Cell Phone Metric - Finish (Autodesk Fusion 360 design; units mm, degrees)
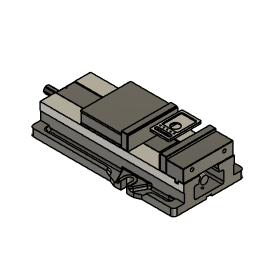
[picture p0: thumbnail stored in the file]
description: HaasClamp
derived_base_feature "Derived Base Feature" bodies "Main Body"
align "Align1"
sketch "Sketch1" plane through (0, 0, 0) normal (0, 0, -1) x axis (1, 0, 0)
  line L1 (30, 46.5) -> (30, -46.5)
  line L2 (-26.5, 50) -> (26.5, 50)
  line L3 (-30, -46.5) -> (-30, 46.5)
  line L4 (26.5, -50) -> (-26.5, -50)
  line L5 (-23.5, 38.5) -> (-23.5, 36)
  line L6 (20, 42) -> (-20, 42)
  line L7 (23.5, 36) -> (23.5, 38.5)
  line L8 (-20, 32.5) -> (20, 32.5)
  line L9 (-50.8, -55) -> (50.8, -55)
  line L10 (-50.8, 55) -> (-50.8, -55)
  line L11 (50.8, 55) -> (-50.8, 55)
  line L12 (50.8, -55) -> (50.8, 55)
  line L13 (-50.8, 55) -> (50.8, -55)
  line L14 (50.8, 55) -> (-50.8, -55)
  arc A1 centre (26.5, -46.5) radius 3.5 clockwise from (30, -46.5) to (26.5, -50)
  arc A2 centre (26.5, 46.5) radius 3.5 clockwise from (26.5, 50) to (30, 46.5)
  arc A3 centre (-26.5, 46.5) radius 3.5 clockwise from (-30, 46.5) to (-26.5, 50)
  arc A4 centre (-26.5, -46.5) radius 3.5 clockwise from (-26.5, -50) to (-30, -46.5)
  circle C1 centre (10.5, 25) radius 2.117
  circle C2 centre (-10.5, 25) radius 2.117
  circle C3 centre (-21, 25) radius 2.117
  circle C4 centre (0, 25) radius 2.117
  circle C5 centre (21, 25) radius 2.117
  arc A5 centre (-20, 38.5) radius 3.5 clockwise from (-23.5, 38.5) to (-20, 42)
  arc A6 centre (20, 38.5) radius 3.5 clockwise from (20, 42) to (23.5, 38.5)
  arc A7 centre (20, 36) radius 3.5 clockwise from (23.5, 36) to (20, 32.5)
  arc A8 centre (-20, 36) radius 3.5 clockwise from (-20, 32.5) to (-23.5, 36)
  circle C6 centre (0, 0) radius 12.5
  point P36 (0, 0)
  point P1 (0, 0)
  point P34 (-50.8, 55)
  point P35 (50.8, 55)
  point P32 (50.8, -55)
  horizontal L9
  perpendicular L9 L10
  parallel L9 L11
  parallel L10 L12
  coincident L13 P36
  coincident L14 P36
  coincident P1 P36
  dimension "d1" distance P34 P35 = 101.6
  dimension "d2" distance P32 P35 = 110
extrude "Extrude1" new body sketch "Sketch1" profile of L9 L10 L11 L12 against normal blind 6 bodies "Stock"
base_feature "Base Feature1"
base_feature "Base Feature1"
base_feature "Base Feature1"
base_feature "Base Feature1"
base_feature "Base Feature1"
base_feature "Base Feature1"
base_feature "Base Feature1"
base_feature "Base Feature1"
base_feature "Base Feature1"
base_feature "Base Feature1"
as_built_joint "As-built1"
as_built_joint "As-built2"
as_built_joint "As-built3"
joint_origin "JointOrigin1" OffsetX 0 OffsetY 0 OffsetZ 0 AngleZ 0
joint "Assemble1" alignAngle 180 alignOffsetX 0 alignOffsetY 0 alignOffsetZ 0 (= "jaw_width_haas_050002") SlideMaximum 22.5 SlideMinimum 0
position "Position1"
sketch "Sketch1" plane through (0, -72.5, 0) normal (0, -1, 0) x axis (1, 0, 0)
  line L1 (75, 73) -> (-75, 73)
  line L2 (76, 74) -> (75, 73)
  line L3 (76, 116.5) -> (76, 74)
  line L4 (75, 117.5) -> (76, 116.5)
  line L5 (-75, 117.5) -> (75, 117.5)
  line L6 (-76, 116.5) -> (-75, 117.5)
  line L7 (-76, 74) -> (-76, 116.5)
  line L8 (-75, 73) -> (-76, 74)
  line L9 (76.4, 114.275) -> (-76, 114.275)
  line L10 (76.4, 73) -> (76.4, 114.275)
  line L11 (-76, 73) -> (76.4, 73)
  line L12 (-76, 114.275) -> (-76, 73)
  circle C1 centre (49.21, 96.8) radius 11
  circle C2 centre (-49.21, 96.8) radius 11
  point P14 (76.4, 73)
  point P12 (-76, 114.275)
  point P13 (76.4, 114.275)
  horizontal L9
  vertical L10
  horizontal L11
  vertical L12
  coincident L1 P14
  coincident L7 P12
  dimension "d16" distance P12 P13 = 152.4
  dimension "d17" distance P13 P14 = 41.275
place_component sketch "Sketch1"
extrude "Extrude1" new body sketch "Sketch1" profile of L1 L2 L3 L7 L8 C1 C2 L9 L11 L12 along normal blind 3.175
place_component sketch "Sketch1"
extrude "Extrude1" sketch "Sketch1" profile of L1 L2 L3 L7 L8 C1 C2 L9 L11 L12 blind -3.175
as_built_joint "As-built5"
as_built_joint "As-built6"
position "Position1"
ground "Pin"
position "Position2"
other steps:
create_component "CreateComponent1"
create_component "CreateComponent2"
create_component "CreateComponent3"
create_component "CreateComponent4"
create_component "CreateComponent5"
create_component "CreateComponent6"
create_component "CreateComponent7"
create_component "CreateComponent8"
create_component "CreateComponent9"
create_component "CreateComponent10"
joint_origin "JointOrigin10"
joint_origin "JointOrigin11"
create_component "CreateComponent11" sketch "Sketch1"
create_component "CreateComponent12" sketch "Sketch1"
create_component "CreateComponent1"
named bodies: "Main Body", "Stock"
